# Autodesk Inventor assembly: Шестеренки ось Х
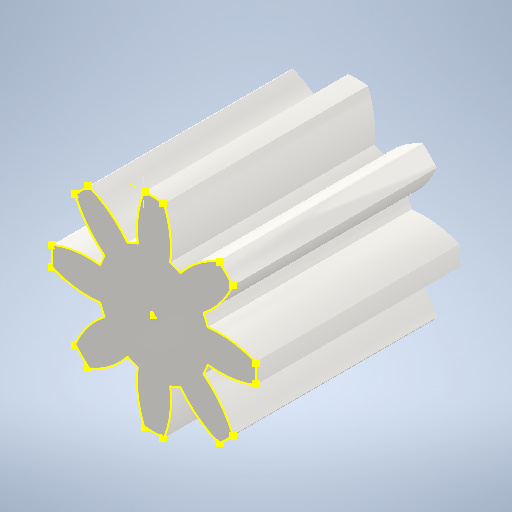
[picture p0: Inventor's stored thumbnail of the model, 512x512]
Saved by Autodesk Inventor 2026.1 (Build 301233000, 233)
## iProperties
Created: 2026-02
Part Number: Шестеренки ось Х
Document SubType Name: Assembly
Designer: Yury Melnikov
Author: Yury Melnikov
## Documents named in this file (2)
- C:\Users\user\Documents\Проекты\ВсОШ_РОБО\Робот V2\Шестеренки ось Х.iam
- C:\Users\user\Documents\Проекты\ВсОШ_РОБО\Робот V2\Шестеренки ось Х\Мастер проектирования\Цилиндрическое зубчатое зацепление1.iam
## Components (1 placed, 1 different names)
1. Цилиндрическое зубчатое зацепление:1 [sub-assembly]
